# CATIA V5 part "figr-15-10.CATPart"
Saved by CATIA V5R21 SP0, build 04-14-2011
Part number: Part1
Bounding box of the stored display mesh (mm): x -50 to 50, y -32.5 to 33.5, z -52 to 1
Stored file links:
  D:\CATIA V5R21 E-RESOURCES\CATIA-V5R21\catia-v5r21-prt\c15-catia-v5r20-prt\c15-catia-v5r21-figr-15-10.CATPart
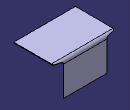
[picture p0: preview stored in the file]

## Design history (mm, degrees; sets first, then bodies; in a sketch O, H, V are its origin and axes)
SheetMetalParameters1: Thickness 1, BendRadius 4, KFactor 0.475772 {= log(min(100,max(20*SheetMetalParameters1.BendRadius,SheetMetalParameters1.Thickness)/SheetMetalParameters1.Thickness))/log(100)/2}, ReliefRadialLength 4, ReliefAxialLength 4, MinimumBendRadius 0
Body1 (main body)
  Sketch1 on xy-plane, origin (0, 0, 0), H (1, 0, 0), V (0, 1, 0)
    line L1 (-50, 32.5) -> (50, 32.5)
    line L2 (50, 32.5) -> (50, -32.5)
    line L3 (50, -32.5) -> (-50, -32.5)
    line L4 (-50, -32.5) -> (-50, 32.5)
    length L1 = 100
    length L2 = 65
    horizontal: L1 H, L3 H
    vertical: L2 V, L4 V
    symmetry: L4 L2 V, L1 L3 H
  Wall1: Thickness 1, Profile Sketch1
  d_NewWallOnEdge1: NewWallOnEdge_Edge edge [face of Wall1 | face of Wall1], NewWallOnEdge_Length 53, NewWallOnEdge_HeightLimitOffset 0, NewWallOnEdge_WidthOffset1 -15, NewWallOnEdge_WidthOffset2 -15, NewWallOnEdge_Angle 90, NewWallOnEdge_BendRadiusValue 4 {= SheetMetalParameters1.BendRadius}, NewWallOnEdge_BendTable SheetMetalParameters1, KFacteur 0.475772 {= log(min(100,max(20*d_NewWallOnEdge1.Radius,SheetMetalParameters1.Thickness)/SheetMetalParameters1.Thickness))/log(100)/2}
